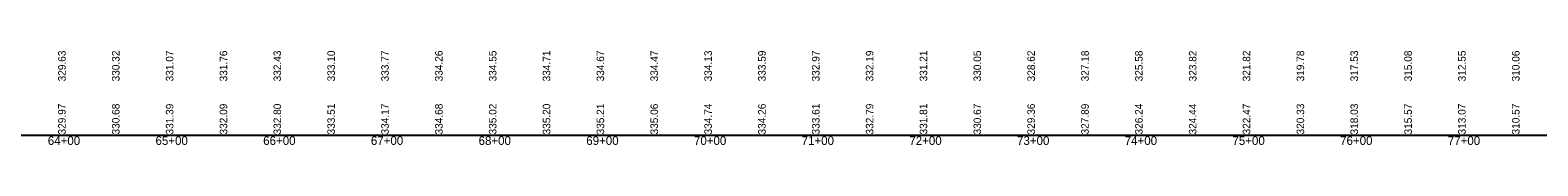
# Model space of a CAD drawing. Extents: x 1876258 to 1932803, y 754739 to 837911.
# Drawn here: x 1884729 to 1886129, y 830495 to 830583 of the extents above; entities that cross this region are included whole.
import ezdxf

# ---------------------------------------------------------------- set-up
doc = ezdxf.new("R2010")
doc.units = 0
for name, color, linetype in [('RD_DDB_StaTX', 7, 'Continuous'), ('RD_DDB_StripGrade', 7, 'Continuous'), ('RD_GPK_Profile_Cell', 7, 'Continuous')]:
    doc.layers.add(name, color=color, linetype=linetype)

msp = doc.modelspace()

# ---------------------------------------------------------------- linework, layer by layer
at = {"layer": 'RD_GPK_Profile_Cell'}
msp.add_line((1878363.1, 830504.3), (1926563.1, 830504.3), dxfattribs=at)

# ---------------------------------------------------------------- texts
at = {"layer": 'RD_DDB_StaTX'}
for s, p in [('64+00', (1884745.5, 830495.3)), ('64+00', (1884745.5, 830495.3)), ('65+00', (1884845.5, 830495.3)), ('65+00', (1884845.5, 830495.3)), ('66+00', (1884945.5, 830495.3)), ('66+00', (1884945.5, 830495.3)), ('67+00', (1885045.5, 830495.3)), ('67+00', (1885045.5, 830495.3)), ('68+00', (1885145.5, 830495.3)), ('68+00', (1885145.5, 830495.3)), ('69+00', (1885245.5, 830495.3)), ('69+00', (1885245.5, 830495.3)), ('70+00', (1885345.5, 830495.3)), ('70+00', (1885345.5, 830495.3)), ('71+00', (1885445.5, 830495.3)), ('71+00', (1885445.5, 830495.3)), ('72+00', (1885545.5, 830495.3)), ('72+00', (1885545.5, 830495.3)), ('73+00', (1885645.5, 830495.3)), ('73+00', (1885645.5, 830495.3)), ('74+00', (1885745.5, 830495.3)), ('74+00', (1885745.5, 830495.3)), ('75+00', (1885845.5, 830495.3)), ('75+00', (1885845.5, 830495.3)), ('76+00', (1885945.5, 830495.3)), ('76+00', (1885945.5, 830495.3)), ('77+00', (1886045.5, 830495.3)), ('77+00', (1886045.5, 830495.3))]:
    msp.add_text(s, height=8, dxfattribs=at).set_placement(p)
at = {"layer": 'RD_DDB_StripGrade'}
for s, p in [('329.63', (1884762.1, 830554.3)), ('330.32', (1884812.1, 830554.3)), ('331.07', (1884862.1, 830554.3)), ('331.76', (1884912.1, 830554.3)), ('332.43', (1884962.1, 830554.3)), ('333.10', (1885012.1, 830554.3)), ('333.77', (1885062.1, 830554.3)), ('334.26', (1885112.1, 830554.3)), ('334.55', (1885162.1, 830554.3)), ('334.71', (1885212.1, 830554.3)), ('334.67', (1885262.1, 830554.3)), ('334.47', (1885312.1, 830554.3)), ('334.13', (1885362.1, 830554.3)), ('333.59', (1885412.1, 830554.3)), ('332.97', (1885462.1, 830554.3)), ('332.19', (1885512.1, 830554.3)), ('331.21', (1885562.1, 830554.3)), ('330.05', (1885612.1, 830554.3)), ('328.62', (1885662.1, 830554.3)), ('327.18', (1885712.1, 830554.3)), ('325.58', (1885762.1, 830554.3)), ('323.82', (1885812.1, 830554.3)), ('321.82', (1885862.1, 830554.3)), ('319.78', (1885912.1, 830554.3)), ('317.53', (1885962.1, 830554.3)), ('315.08', (1886012.1, 830554.3)), ('312.55', (1886062.1, 830554.3)), ('310.06', (1886112.1, 830554.3)), ('329.97', (1884762.1, 830505)), ('330.68', (1884812.1, 830505)), ('331.39', (1884862.1, 830505)), ('332.09', (1884912.1, 830505)), ('332.80', (1884962.1, 830505)), ('333.51', (1885012.1, 830505)), ('334.17', (1885062.1, 830505)), ('334.68', (1885112.1, 830505)), ('335.02', (1885162.1, 830505)), ('335.20', (1885212.1, 830505)), ('335.21', (1885262.1, 830505)), ('335.06', (1885312.1, 830505)), ('334.74', (1885362.1, 830505)), ('334.26', (1885412.1, 830505)), ('333.61', (1885462.1, 830505)), ('332.79', (1885512.1, 830505)), ('331.81', (1885562.1, 830505)), ('330.67', (1885612.1, 830505)), ('329.36', (1885662.1, 830505)), ('327.89', (1885712.1, 830505)), ('326.24', (1885762.1, 830505)), ('324.44', (1885812.1, 830505)), ('322.47', (1885862.1, 830505)), ('320.33', (1885912.1, 830505)), ('318.03', (1885962.1, 830505)), ('315.57', (1886012.1, 830505)), ('313.07', (1886062.1, 830505)), ('310.57', (1886112.1, 830505))]:
    msp.add_text(s, height=7, rotation=90, dxfattribs=at).set_placement(p)

doc.saveas('drawing.dxf')
